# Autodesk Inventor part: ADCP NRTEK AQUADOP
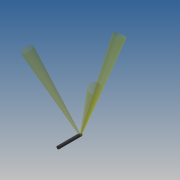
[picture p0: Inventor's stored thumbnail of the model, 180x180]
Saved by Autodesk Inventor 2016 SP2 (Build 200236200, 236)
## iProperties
Company: NIWA Instrument Systems
Created: 2020-09
Part Number: ADCP NRTEK AQUADOP
Material: Acetal Resin, Black
Document SubType Name: Modeling
Designer: BS
Manufacturer: Standard
Standards Organization: Custom
Mass: 2700 g
Surface Area: 1502.63 cm^2
Volume: 2578.08 cm^3
Density: 1.425 g/cm^3
Appearance: Dark Gray
Description: ADCP NRTEK AQUADOP
in_water_weight: 0.2
Author: BS
Revision Number: 1
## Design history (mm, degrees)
sketch "Sketch1"
  geometry: L1 (0, 0)-(0, -628); L2 (0, -628)-(-37.5, -628); L3 (-37.5, -628)-(-37.5, -37.5); A1 r 37.5 centre (0, -37.5) between (0, 0) and (-37.5, -37.5)
  constraints: 6 end point, 2 perpendicular, 2 point on circle, 1 centre point, 1 tangent, 1 vertical
  dimensions: "d0" = 628 distance of L1.start L1.end; "d1" = 75 diameter of L3 L1; "d2" = 37.5 radius of A1
revolve "Revolution1" sketch "Sketch1" stored, may be unused: angle "d3" = 90 deg
sketch "Sketch2"
  geometry: L1 (0, 0)-(-63, 0); L2 (-78, 15)-(-78, 37.5); L3 (-628, -37.5)-(-628, 37.5) reference; L4 (-628, 37.5)-(-37.5, 37.5) reference; L5 (-37.5, -37.5)-(-628, -37.5) reference; A1 r 15 centre (-63, 15) between (-78, 15) and (-63, 0); A2 r 37.5 centre (-37.5, 0) between (-37.5, -37.5) and (0, 0) reference; A3 r 37.5 centre (-37.5, 0) between (0, 0) and (-37.5, 37.5) reference
  constraints: 4 end point, 2 point on circle, 2 tangent, 1 centre point, 1 horizontal, 1 perpendicular, 1 point on line
  dimensions: "d4" = 550 distance between parallel lines of L3 L2; "d5" = 15 radius of A1
extrude "Extrusion1" cut sketch "Sketch2" stored distance "d6" = 10; taper "d7" = 0 deg
sketch "Sketch6"
  geometry: L1 (-37.5, 0)-(-37.5, 21.651); L2 (-37.5, 0)-(0, 0) reference; L3 (-37.5, 21.651)-(0, 0); L4 (0, 0)-(-37.5, 0)
  constraints: 6 end point, 1 collinear, 1 vertical
  dimensions: "d14" = 30 deg angle of L3 L2
revolve "Revolution2" sketch "Sketch6" stored, may be unused: angle "d15" = 90 deg
workplane "Work Plane2"
sketch "Sketch7" dims "d17" = 35
  geometry: 6 further points; 1 other entity
  constraints: 2 vertical alignment, 4 other
extrude "Extrusion3" join sketch "Sketch7" distance "d18" = 10; taper "d19" = 0 deg
sketch "Sketch8"
  geometry: A1 r 17.5 centre (0, -17.5) between (0, 0) and (0, -35) reference; A2 r 17.5 centre (0, -17.5) between (0, -35) and (0, 0) reference; 1 further point
extrude_surface "ExtrusionSrf1" sketch "Sketch8" dims "d23" = 2000, "d24" = 0.59341
pattern_circular "Circular Pattern1" dims angle "d21" = 360 deg
sketch "Sketch4"
  geometry: L1 (37.5, -590.5)-(-37.5, -590.5) reference; L2 (-37.5, -590.5)-(-37.5, -25.5) reference; L3 (37.5, -25.5)-(-37.5, -25.5) reference; L4 (37.5, 0)-(37.5, -25.5) reference; L5 (-37.5, -25.5)-(-37.5, 0) reference; L6 (37.5, -25.5)-(37.5, -590.5) reference; L7 (-32.476, 18.75)-(32.476, 18.75); L8 (32.476, 18.75)-(0, -37.5); L9 (0, -37.5)-(-32.476, 18.75); A1 r 37.5 centre (0, 0) between (37.5, 0) and (-37.5, 0) reference; 2 further points
  constraints: 6 end point, 1 coincident, 1 horizontal, 1 point on circle, 7 other
  node "Project Cut Edges3"
workplane "Work Plane1"
sketch "Sketch5"
  geometry: L1 (34.369, -590.5)-(-34.369, -590.5) reference; L2 (-34.369, -590.5)-(-34.369, -40.5) reference; L3 (-34.369, -40.5)-(34.369, -40.5) reference; L4 (34.369, -40.5)-(34.369, -590.5) reference; L5 (-9.808, 5.663)-(9.808, 5.663); L6 (9.808, 5.663)-(0, -11.325); L7 (0, -11.325)-(-9.808, 5.663); L8 (37.5, 0)-(-37.5, 0) reference; 3 further points
  constraints: 6 end point, 1 coincident, 1 horizontal, 1 midpoint, 7 other
  node "Project Cut Edges4"
body "Solid1"
node "Projected Loop1"
body "Srf1"
body "Srf2"
body "Srf3"
node "Project Cut Edges1"
extrude_surface "ExtrusionSrf2"
extrude_surface "ExtrusionSrf3"
other parameters: "d13" = 15, "d16" = -30 deg
